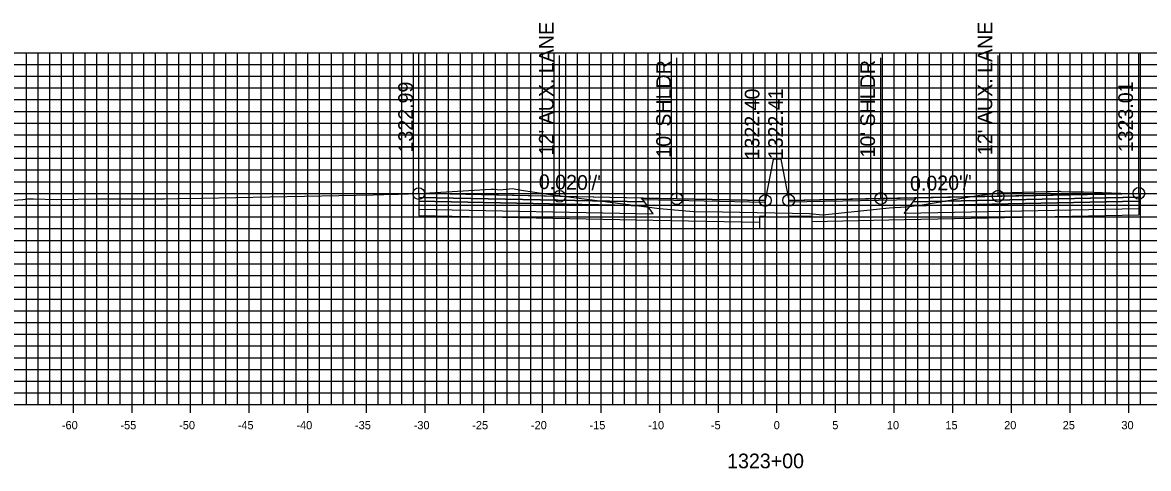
# Model space of a CAD drawing. Extents: x 674939 to 678919, y 750652 to 765176.
# Drawn here: x 678674.2 to 678770.2, y 751447.1 to 751485.1 of the extents above; entities that cross this region are included whole.
import ezdxf

# ---------------------------------------------------------------- set-up
doc = ezdxf.new("R2010")
doc.units = 0
for name, color, linetype in [('Level 10', 7, 'Continuous'), ('Level 17', 7, 'Continuous'), ('Level 18', 7, 'Continuous'), ('Level 19', 7, 'Continuous'), ('Level 20', 7, 'Continuous'), ('Level 22', 7, 'Continuous'), ('Level 23', 7, 'Continuous'), ('Level 4', 7, 'Continuous'), ('Level 8', 7, 'Continuous'), ('Level 9', 7, 'Continuous')]:
    doc.layers.add(name, color=color, linetype=linetype)

msp = doc.modelspace()

# ---------------------------------------------------------------- linework, layer by layer
at = {"layer": 'Level 10'}
msp.add_lwpolyline([(678669.435, 751469.723), (678674.22, 751470.046), (678674.631, 751470.095), (678675.137, 751470.096), (678677.107, 751470.035), (678678.951, 751470.064), (678680.54, 751470.084), (678684.772, 751470.087), (678684.839, 751470.088), (678684.864, 751470.089), (678686.289, 751470.106), (678687.437, 751470.122), (678689.46, 751470.155), (678704.084, 751470.443), (678705.009, 751470.464), (678706.251, 751470.491), (678707.987, 751470.541), (678707.994, 751470.541), (678714.129, 751470.914), (678714.258, 751470.916), (678714.388, 751470.916), (678714.427, 751470.92), (678714.934, 751470.869), (678715.941, 751470.96), (678716.912, 751470.809), (678719.218, 751470.456), (678728.504, 751469.281), (678731.427, 751469.015), (678733.881, 751468.974), (678741.318, 751468.84), (678742.401, 751468.74), (678748.1, 751469.328), (678749.588, 751469.423), (678750.905, 751469.586), (678755.838, 751470.407), (678757.519, 751470.608), (678761.543, 751470.718), (678761.85, 751470.713), (678762.457, 751470.745), (678762.659, 751470.748), (678762.736, 751470.732), (678763.646, 751470.698), (678764.656, 751470.686), (678767.866, 751470.589), (678769.078, 751470.561), (678769.389, 751470.559), (678769.544, 751470.554), (678770.142, 751470.549), (678772.123, 751470.509)], dxfattribs=at)
at = {"layer": 'Level 17'}
for points in [[(678738.203, 751473.45), (678737.533, 751469.95)], [(678738.863, 751473.462), (678738.863, 751473.462), (678738.203, 751473.462), (678738.203, 751473.45)], [(678738.863, 751473.462), (678739.533, 751469.962)], [(678737.533, 751469.95), (678737.533, 751468.575), (678737.033, 751468.575), (678737.033, 751467.575), (678741.533, 751467.575), (678741.533, 751468.575), (678739.533, 751468.575), (678739.533, 751469.962)]]:
    msp.add_lwpolyline(points, dxfattribs=at)
at = {"layer": 'Level 18'}
for points in [[(678737.533, 751469.95), (678729.987, 751470.101), (678719.987, 751470.301), (678707.987, 751470.541)], [(678769.389, 751470.559), (678757.389, 751470.319), (678747.389, 751470.119), (678739.533, 751469.962)]]:
    msp.add_lwpolyline(points, dxfattribs=at)
for points in [[(678707.987, 751470.541), (678707.987, 751470.211), (678727.237, 751469.826), (678726.987, 751470.161)], [(678769.389, 751470.559), (678769.389, 751470.229), (678750.139, 751469.844), (678750.389, 751470.179)], [(678726.987, 751470.161), (678737.533, 751469.95), (678737.537, 751469.793), (678727.107, 751470.001)], [(678750.27, 751470.019), (678739.533, 751469.804), (678739.533, 751469.962), (678750.389, 751470.179)]]:
    msp.add_lwpolyline(points, close=True, dxfattribs=at)
at = {"layer": 'Level 19'}
for points in [[(678707.987, 751470.211), (678707.987, 751469.881), (678727.487, 751469.491), (678727.237, 751469.826)], [(678707.987, 751469.881), (678707.987, 751469.221), (678727.987, 751468.821), (678727.487, 751469.491)], [(678769.389, 751469.899), (678769.389, 751469.239), (678749.389, 751468.839), (678749.889, 751469.509)], [(678769.389, 751470.229), (678769.389, 751469.899), (678749.889, 751469.509), (678750.139, 751469.844)]]:
    msp.add_lwpolyline(points, close=True, dxfattribs=at)
for points in [[(678707.987, 751469.221), (678707.987, 751468.681), (678727.987, 751468.281), (678737.033, 751468.1)], [(678769.389, 751469.239), (678769.389, 751468.699), (678749.389, 751468.299), (678741.533, 751468.142)]]:
    msp.add_lwpolyline(points, dxfattribs=at)
at = {"layer": 'Level 20'}
for p, q in [((678638.533, 751482.551), (678838.533, 751482.551)), ((678674.533, 751452.551), (678674.533, 751482.551)), ((678675.533, 751452.551), (678675.533, 751482.551)), ((678676.533, 751452.551), (678676.533, 751482.551)), ((678677.533, 751452.551), (678677.533, 751482.551)), ((678678.533, 751452.551), (678678.533, 751482.551)), ((678679.533, 751452.551), (678679.533, 751482.551)), ((678680.533, 751452.551), (678680.533, 751482.551)), ((678681.533, 751452.551), (678681.533, 751482.551)), ((678682.533, 751452.551), (678682.533, 751482.551)), ((678683.533, 751452.551), (678683.533, 751482.551)), ((678684.533, 751452.551), (678684.533, 751482.551)), ((678685.533, 751452.551), (678685.533, 751482.551)), ((678686.533, 751452.551), (678686.533, 751482.551)), ((678687.533, 751452.551), (678687.533, 751482.551)), ((678688.533, 751452.551), (678688.533, 751482.551)), ((678689.533, 751452.551), (678689.533, 751482.551)), ((678690.533, 751452.551), (678690.533, 751482.551)), ((678691.533, 751452.551), (678691.533, 751482.551)), ((678692.533, 751452.551), (678692.533, 751482.551)), ((678693.533, 751452.551), (678693.533, 751482.551)), ((678694.533, 751452.551), (678694.533, 751482.551)), ((678695.533, 751452.551), (678695.533, 751482.551)), ((678696.533, 751452.551), (678696.533, 751482.551)), ((678697.533, 751452.551), (678697.533, 751482.551)), ((678698.533, 751452.551), (678698.533, 751482.551)), ((678699.533, 751452.551), (678699.533, 751482.551)), ((678700.533, 751452.551), (678700.533, 751482.551)), ((678701.533, 751452.551), (678701.533, 751482.551)), ((678702.533, 751452.551), (678702.533, 751482.551)), ((678703.533, 751452.551), (678703.533, 751482.551)), ((678704.533, 751452.551), (678704.533, 751482.551)), ((678705.533, 751452.551), (678705.533, 751482.551)), ((678706.533, 751452.551), (678706.533, 751482.551)), ((678707.533, 751452.551), (678707.533, 751482.551)), ((678708.533, 751452.551), (678708.533, 751482.551)), ((678709.533, 751452.551), (678709.533, 751482.551)), ((678710.533, 751452.551), (678710.533, 751482.551)), ((678711.533, 751452.551), (678711.533, 751482.551)), ((678712.533, 751452.551), (678712.533, 751482.551)), ((678713.533, 751452.551), (678713.533, 751482.551)), ((678714.533, 751452.551), (678714.533, 751482.551)), ((678715.533, 751452.551), (678715.533, 751482.551)), ((678716.533, 751452.551), (678716.533, 751482.551)), ((678717.533, 751452.551), (678717.533, 751482.551)), ((678718.533, 751452.551), (678718.533, 751482.551)), ((678719.533, 751452.551), (678719.533, 751482.551)), ((678720.533, 751452.551), (678720.533, 751482.551)), ((678721.533, 751452.551), (678721.533, 751482.551)), ((678722.533, 751452.551), (678722.533, 751482.551)), ((678723.533, 751452.551), (678723.533, 751482.551)), ((678724.533, 751452.551), (678724.533, 751482.551)), ((678725.533, 751452.551), (678725.533, 751482.551)), ((678726.533, 751452.551), (678726.533, 751482.551)), ((678727.533, 751452.551), (678727.533, 751482.551)), ((678728.533, 751452.551), (678728.533, 751482.551)), ((678729.533, 751452.551), (678729.533, 751482.551)), ((678730.533, 751452.551), (678730.533, 751482.551)), ((678731.533, 751452.551), (678731.533, 751482.551)), ((678732.533, 751452.551), (678732.533, 751482.551)), ((678733.533, 751452.551), (678733.533, 751482.551)), ((678734.533, 751452.551), (678734.533, 751482.551)), ((678735.533, 751452.551), (678735.533, 751482.551)), ((678736.533, 751452.551), (678736.533, 751482.551)), ((678737.533, 751452.551), (678737.533, 751482.551)), ((678738.533, 751452.551), (678738.533, 751482.551)), ((678739.533, 751452.551), (678739.533, 751482.551)), ((678740.533, 751452.551), (678740.533, 751482.551)), ((678741.533, 751452.551), (678741.533, 751482.551)), ((678742.533, 751452.551), (678742.533, 751482.551)), ((678743.533, 751452.551), (678743.533, 751482.551)), ((678744.533, 751452.551), (678744.533, 751482.551)), ((678745.533, 751452.551), (678745.533, 751482.551)), ((678746.533, 751452.551), (678746.533, 751482.551)), ((678747.533, 751452.551), (678747.533, 751482.551)), ((678748.533, 751452.551), (678748.533, 751482.551)), ((678749.533, 751452.551), (678749.533, 751482.551)), ((678750.533, 751452.551), (678750.533, 751482.551)), ((678751.533, 751452.551), (678751.533, 751482.551)), ((678752.533, 751452.551), (678752.533, 751482.551)), ((678753.533, 751452.551), (678753.533, 751482.551)), ((678754.533, 751452.551), (678754.533, 751482.551)), ((678755.533, 751452.551), (678755.533, 751482.551)), ((678756.533, 751452.551), (678756.533, 751482.551)), ((678757.533, 751452.551), (678757.533, 751482.551)), ((678758.533, 751452.551), (678758.533, 751482.551)), ((678759.533, 751452.551), (678759.533, 751482.551)), ((678760.533, 751452.551), (678760.533, 751482.551)), ((678761.533, 751452.551), (678761.533, 751482.551)), ((678762.533, 751452.551), (678762.533, 751482.551)), ((678763.533, 751452.551), (678763.533, 751482.551)), ((678764.533, 751452.551), (678764.533, 751482.551)), ((678765.533, 751452.551), (678765.533, 751482.551)), ((678766.533, 751452.551), (678766.533, 751482.551)), ((678767.533, 751452.551), (678767.533, 751482.551)), ((678768.533, 751452.551), (678768.533, 751482.551)), ((678769.533, 751452.551), (678769.533, 751482.551)), ((678638.533, 751481.551), (678838.533, 751481.551)), ((678638.533, 751480.551), (678838.533, 751480.551)), ((678638.533, 751479.551), (678838.533, 751479.551)), ((678638.533, 751478.551), (678838.533, 751478.551)), ((678638.533, 751477.551), (678838.533, 751477.551)), ((678638.533, 751476.551), (678838.533, 751476.551)), ((678638.533, 751475.551), (678838.533, 751475.551)), ((678638.533, 751474.551), (678838.533, 751474.551)), ((678638.533, 751473.551), (678838.533, 751473.551)), ((678638.533, 751472.551), (678838.533, 751472.551)), ((678638.533, 751471.551), (678838.533, 751471.551)), ((678638.533, 751470.551), (678838.533, 751470.551)), ((678638.533, 751469.551), (678838.533, 751469.551)), ((678638.533, 751468.551), (678838.533, 751468.551)), ((678638.533, 751467.551), (678838.533, 751467.551)), ((678638.533, 751466.551), (678838.533, 751466.551)), ((678638.533, 751465.551), (678838.533, 751465.551)), ((678638.533, 751464.551), (678838.533, 751464.551)), ((678638.533, 751463.551), (678838.533, 751463.551)), ((678638.533, 751462.551), (678838.533, 751462.551)), ((678638.533, 751461.551), (678838.533, 751461.551)), ((678638.533, 751460.551), (678838.533, 751460.551)), ((678638.533, 751459.551), (678838.533, 751459.551)), ((678638.533, 751458.551), (678838.533, 751458.551)), ((678638.533, 751457.551), (678838.533, 751457.551)), ((678638.533, 751456.551), (678838.533, 751456.551)), ((678638.533, 751455.551), (678838.533, 751455.551)), ((678638.533, 751454.551), (678838.533, 751454.551)), ((678638.533, 751453.551), (678838.533, 751453.551)), ((678638.533, 751452.551), (678838.533, 751452.551))]:
    msp.add_line(p, q, dxfattribs=at)
at = {"layer": 'Level 23'}
for p, q in [((678707.987, 751470.541), (678707.987, 751482.541)), ((678719.987, 751470.301), (678719.987, 751482.301)), ((678729.987, 751470.101), (678729.987, 751482.101)), ((678737.533, 751469.95), (678737.533, 751481.95)), ((678739.533, 751469.962), (678739.533, 751481.962)), ((678747.389, 751470.119), (678747.389, 751482.119)), ((678757.389, 751470.319), (678757.389, 751482.319)), ((678769.389, 751470.559), (678769.389, 751482.559))]:
    msp.add_line(p, q, dxfattribs=at)
at = {"layer": 'Level 4'}
for centre in [(678707.987, 751470.541), (678719.987, 751470.301), (678729.987, 751470.101), (678737.533, 751469.95), (678739.533, 751469.962), (678747.389, 751470.119), (678757.389, 751470.319), (678769.389, 751470.559)]:
    msp.add_circle(centre, 0.5, dxfattribs=at)
at = {"layer": 'Level 8'}
for p, q in [((678678.533, 751451.851), (678678.533, 751453.251)), ((678683.533, 751451.851), (678683.533, 751453.251)), ((678688.533, 751451.851), (678688.533, 751453.251)), ((678693.533, 751451.851), (678693.533, 751453.251)), ((678698.533, 751451.851), (678698.533, 751453.251)), ((678703.533, 751451.851), (678703.533, 751453.251)), ((678708.533, 751451.851), (678708.533, 751453.251)), ((678713.533, 751451.851), (678713.533, 751453.251)), ((678718.533, 751451.851), (678718.533, 751453.251)), ((678723.533, 751451.851), (678723.533, 751453.251)), ((678728.533, 751451.851), (678728.533, 751453.251)), ((678733.533, 751451.851), (678733.533, 751453.251)), ((678738.533, 751451.851), (678738.533, 751453.251)), ((678743.533, 751451.851), (678743.533, 751453.251)), ((678748.533, 751451.851), (678748.533, 751453.251)), ((678753.533, 751451.851), (678753.533, 751453.251)), ((678758.533, 751451.851), (678758.533, 751453.251)), ((678763.533, 751451.851), (678763.533, 751453.251)), ((678768.533, 751451.851), (678768.533, 751453.251)), ((678638.533, 751452.551), (678838.533, 751452.551))]:
    msp.add_line(p, q, dxfattribs=at)

# ---------------------------------------------------------------- texts
at = {"layer": 'Level 22'}
for rotation, p in [(358.85424, (678718.21, 751470.937)), (1.14576, (678749.887, 751470.769))]:
    msp.add_text("0.020'/'", height=1.25, rotation=rotation, dxfattribs=at).set_placement(p)
at = {"layer": 'Level 23'}
for s, p in [("12' AUX. LANE", (678719.487, 751473.801)), ("12' AUX. LANE", (678756.889, 751473.819)), ("10' SHLDR", (678729.487, 751473.601)), ("10' SHLDR", (678746.889, 751473.619)), ('1322.99', (678707.487, 751474.041)), ('1323.01', (678768.889, 751474.059)), ('1322.40', (678737.033, 751473.45)), ('1322.41', (678739.033, 751473.462))]:
    msp.add_text(s, height=1.25, rotation=90, dxfattribs=at).set_placement(p)
at = {"layer": 'Level 9'}
for s, height, p in [('-60', 0.7, (678677.552, 751450.451)), ('-55', 0.7, (678682.546, 751450.451)), ('-50', 0.7, (678687.552, 751450.451)), ('-45', 0.7, (678692.546, 751450.451)), ('-40', 0.7, (678697.552, 751450.451)), ('-35', 0.7, (678702.546, 751450.451)), ('-30', 0.7, (678707.552, 751450.451)), ('-25', 0.7, (678712.546, 751450.451)), ('-20', 0.7, (678717.552, 751450.451)), ('-15', 0.7, (678722.546, 751450.451)), ('-10', 0.7, (678727.552, 751450.451)), ('-5', 0.7, (678732.896, 751450.451)), ('0', 0.7, (678738.252, 751450.451)), ('5', 0.7, (678743.246, 751450.451)), ('10', 0.7, (678747.902, 751450.451)), ('15', 0.7, (678752.896, 751450.451)), ('20', 0.7, (678757.902, 751450.451)), ('25', 0.7, (678762.896, 751450.451)), ('30', 0.7, (678767.902, 751450.451)), ('1323+00', 1.25, (678734.281, 751447.126))]:
    msp.add_text(s, height=height, dxfattribs=at).set_placement(p)

doc.saveas('drawing.dxf')
